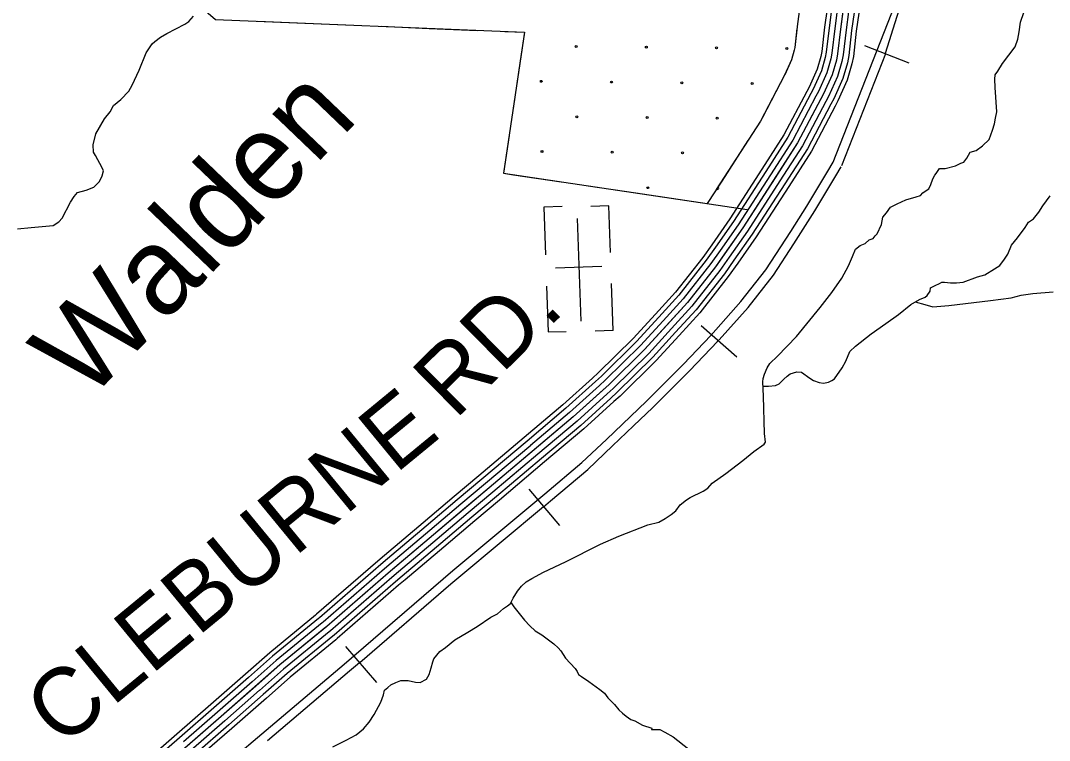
# Model space of a CAD drawing. Extents: x 1577619 to 1828281, y 483481 to 598136.
# Drawn here: x 1675742 to 1681374, y 510126 to 514068 of the extents above; entities that cross this region are included whole.
import ezdxf

# ---------------------------------------------------------------- set-up
doc = ezdxf.new("R2010")
doc.units = 0
for name, color, linetype in [('DESIGN - CONTOURS - Intermediate with optional Text', 7, 'Continuous'), ('DESIGN - DRAINAGE - Bridges and Cross Drains Size Text', 7, 'Continuous'), ('DESIGN - EROSION CONTROL - Devices', 7, 'Continuous'), ('DESIGN - ROW - Right-of-Way and Easement Labels', 7, 'Continuous'), ('DESIGN - TRANSPORTATION - Text', 7, 'Continuous'), ('DESIGN - UTILITIES - Cable (Underground) with Text', 7, 'Continuous'), ('SURVEY - TRANSPORTATION - Roads', 7, 'Continuous'), ('SURVEY - VEGETATION - Features with Text', 7, 'Continuous')]:
    doc.layers.add(name, color=color, linetype=linetype)

msp = doc.modelspace()

# ---------------------------------------------------------------- linework, layer by layer
at = {"layer": 'DESIGN - CONTOURS - Intermediate with optional Text'}
for p, q in [((1680362.2, 513931.6), (1680604.2, 513836.6)), ((1679662.5, 512223.8), (1679467.7, 512395.9)), ((1678693.2, 511302.3), (1678526.6, 511502)), ((1677692.7, 510443.5), (1677522.8, 510640.3))]:
    msp.add_line(p, q, dxfattribs=at)
for points in [[(1680189.5, 513292.2), (1680607.7, 514357.5), (1680665.4, 514468.9), (1680691.8, 514511.6), (1680818, 514688.1), (1680909.7, 514821.1), (1681031.8, 514985.7), (1681222.8, 515221.4), (1681354.8, 515377.9), (1681517, 515547.9), (1681654.6, 515676.2), (1681889.3, 515891.4), (1682077.3, 516051), (1682307.4, 516222.2), (1682599.6, 516406.5), (1682925.9, 516594.3), (1683175.5, 516727.1), (1683431, 516853.8), (1683670.2, 516958.7), (1683862.5, 517052.8)], [(1680476.4, 513888.6), (1680603.4, 514296.5), (1680640.9, 514394.1), (1680689.7, 514510.4)], [(1680236.8, 513273.6), (1680477.9, 513888)], [(1674951, 508587.6), (1675078.1, 508661.1), (1675481.1, 508901.7), (1675782.4, 509112.4), (1676046.1, 509313.4), (1676456.1, 509648.1), (1677512.9, 510542.5), (1678108.9, 511056.8), (1678611.5, 511476.1), (1678813.4, 511646.9), (1678948.4, 511774.5), (1679168.8, 511983.5), (1679370.4, 512186.2), (1679519.7, 512344), (1679684, 512530.1), (1679821.1, 512703.3), (1679957.3, 512912.7), (1680046.6, 513052.1), (1680161.2, 513242.5), (1680189.5, 513292.2)], [(1679974.1, 512845.8), (1679999.8, 512885.3), (1680089.6, 513025.4), (1680204.8, 513216.9), (1680233.5, 513267.1)], [(1679566.5, 512318.6), (1679723.8, 512496.8), (1679863.3, 512673), (1679975.2, 512845.1)], [(1679097.6, 511848), (1679203.2, 511948.2), (1679405.8, 512151.9), (1679556.1, 512310.7), (1679564.6, 512320.3)], [(1678603.9, 511405.6), (1678643.1, 511438.4), (1678846.3, 511610.2), (1678982.2, 511738.7), (1679097.5, 511848.1)], [(1678098, 510983.1), (1678140.4, 511019.7), (1678603.6, 511406)], [(1677598.2, 510552), (1678097.9, 510983.2)], [(1677093.4, 510126.1), (1677543.3, 510506.9), (1677597.1, 510553.3)]]:
    msp.add_lwpolyline(points, dxfattribs=at)
at = {"layer": 'DESIGN - EROSION CONTROL - Devices'}
for centre in [(1678782.8, 513925.3), (1679167.3, 513921.6), (1679551.9, 513917.8), (1679936.4, 513914.1), (1678592.4, 513734.9), (1678976.9, 513731.2), (1679361.5, 513727.4), (1679746, 513723.7), (1678786.5, 513540.7), (1679171.1, 513537), (1679555.6, 513533.3), (1678596.1, 513350.3), (1678980.7, 513346.6), (1679365.2, 513342.9), (1679174.8, 513152.5)]:
    msp.add_circle(centre, 5.28, dxfattribs=at)
msp.add_arc((1679559.4, 513148.7), 5.28, 0.5655, 293.7882, dxfattribs=at)
at = {"layer": 'DESIGN - TRANSPORTATION - Text'}
for points in [[(1678605.1, 511046.9), (1678725.6, 511103.5), (1678916.5, 511201.3), (1679016.9, 511244.1), (1679175.4, 511306.2), (1679235.4, 511321.5), (1679269.6, 511341.1), (1679303.8, 511362.7), (1679328, 511382.4), (1679352.4, 511416.2), (1679386.7, 511443.8), (1679406.8, 511455.5), (1679479.1, 511490.7), (1679503.2, 511506.4), (1679527.5, 511534.1), (1679602, 511587.3), (1679694.7, 511658.2), (1679755.2, 511707.5), (1679811.6, 511748.9), (1679819.7, 511758.8), (1679814.3, 511806.9), (1679808.8, 512011.2), (1679805.7, 512089.4), (1679805.9, 512107.4), (1679814.2, 512131.3), (1679828.6, 512165.2), (1679842.8, 512189), (1679885.3, 512230.6), (1679988.4, 512337.4), (1680118.1, 512496), (1680183, 512579.3), (1680237.8, 512656.7), (1680274.6, 512724.3), (1680295.1, 512776.1), (1680311.6, 512816), (1680337.8, 512835.7), (1680365.9, 512847.4), (1680386.1, 512867.1), (1680408.1, 512874.9), (1680420.3, 512888.7), (1680430.4, 512900.6), (1680455, 512950.4), (1680461.4, 512990.3), (1680481.7, 513014.1), (1680504, 513045.9), (1680540.2, 513063.5), (1680588.4, 513086.9), (1680644.5, 513102.2), (1680668.5, 513109.9), (1680680.7, 513123.8), (1680698.8, 513137.6), (1680712.9, 513145.4), (1680725.2, 513169.3), (1680735.5, 513201.2), (1680745.7, 513221.1), (1680753.9, 513231), (1680772.1, 513256.8), (1680802.1, 513258.5), (1680860.2, 513271.8), (1680888.3, 513287.4), (1680904.4, 513293.2), (1680920.6, 513315.1), (1680939, 513346.9), (1680973, 513356.5), (1681007.3, 513382.1), (1681043.6, 513415.7), (1681062.2, 513467.5), (1681072.6, 513501.4), (1681079, 513533.4), (1681085.4, 513567.3), (1681077, 513701.6), (1681075.5, 513747.7), (1681075.8, 513769.7), (1681092, 513791.5), (1681116.5, 513833.3), (1681151, 513878.9), (1681185.5, 513924.5), (1681199.9, 513966.4), (1681208.4, 514006.3), (1681215, 514058.3), (1681233.6, 514112.2)], [(1675725.8, 512928.1), (1675799.7, 512935.2), (1675919.7, 512945.7), (1675951.9, 512965.3), (1675970.1, 512985.1), (1676015, 513072.7), (1676035.4, 513104.5), (1676053.6, 513126.3), (1676101.7, 513139.7), (1676143.8, 513155.2), (1676174.2, 513186.8), (1676188.5, 513216.7), (1676196.8, 513244.6), (1676189, 513260.8), (1676151.9, 513329.3), (1676142.1, 513347.4), (1676138.6, 513387.5), (1676153.3, 513447.4), (1676202.2, 513528.9), (1676232.6, 513568.6), (1676251, 513602.4), (1676291.3, 513635.9), (1676333.8, 513681.5), (1676352.2, 513713.3), (1676391.1, 513796.9), (1676430.2, 513890.5), (1676462.7, 513940.2), (1676476.8, 513954), (1676507.1, 513977.7), (1676543.2, 513997.3), (1676641.7, 514048.1), (1676663.8, 514061.8), (1676688.1, 514091.6)], [(1679806.5, 512066), (1679835.1, 512066.4), (1679875.1, 512070), (1679895.2, 512077.7), (1679919.4, 512103.4), (1679937.6, 512121.2), (1679953.7, 512133.1), (1679991.8, 512144.6), (1680015.8, 512142.3), (1680061.3, 512109.7), (1680083.1, 512097.4), (1680112.9, 512085), (1680136.9, 512082.7), (1680164.9, 512088.4), (1680182.9, 512096.2), (1680197, 512106), (1680239.7, 512165.6), (1680260.1, 512203.4), (1680280.7, 512255.2), (1680313, 512284.8), (1680397.7, 512351.8), (1680478.2, 512408.9), (1680546.7, 512458.1), (1680615.3, 512513.4), (1680661.5, 512540.8), (1680693.6, 512552.4), (1680703.7, 512562.3), (1680720, 512586.2), (1680722.2, 512604.1), (1680748.3, 512617.8), (1680772.4, 512627.6), (1680784.4, 512635.4), (1680798.4, 512635.2), (1680832.3, 512630.8), (1680864.3, 512632.4), (1680902.3, 512636), (1680980.5, 512665), (1681020.6, 512674.6), (1681072.9, 512708), (1681103, 512725.6), (1681127.4, 512761.3), (1681145.7, 512789.2), (1681166.3, 512837), (1681198.7, 512878.6), (1681241.3, 512934.1), (1681259.6, 512963.9), (1681285.8, 512981.6), (1681316.2, 513019.3), (1681336.6, 513053.1), (1681377.2, 513108.7)], [(1680638.8, 512527.3), (1680691.1, 512512.4), (1680734.9, 512499.9), (1680822.9, 512506.8), (1681050.8, 512534), (1681164.8, 512548.6), (1681218.9, 512564), (1681282.9, 512573.2), (1681394.9, 512581.8)], [(1677451.5, 510090), (1677523.8, 510127.2), (1677578.1, 510156.5), (1677618.4, 510190.1), (1677650.8, 510225.7), (1677677.3, 510267.4), (1677714, 510335.1), (1677728.5, 510374.9), (1677734.8, 510400.9), (1677752.9, 510414.7), (1677769.1, 510430.5), (1677795.2, 510442.2), (1677823.3, 510453.9), (1677863.2, 510453.4), (1677903, 510444.9), (1677929, 510442.5), (1677963.2, 510462.1), (1677979.4, 510486), (1677989.9, 510523.9), (1677998.2, 510555.8), (1678004.4, 510571.8), (1678036.8, 510613.4), (1678067.1, 510635.1), (1678119.5, 510676.5), (1678189.9, 510717.7), (1678242.1, 510749), (1678316.6, 510800.2), (1678352.8, 510819.8), (1678385.1, 510847.4), (1678407.3, 510863.2), (1678423.4, 510875), (1678437.7, 510904.8), (1678462.1, 510942.6), (1678484.4, 510970.3), (1678508.7, 510994.1), (1678540.8, 511011.7), (1678605.1, 511046.9)], [(1678427.7, 510879.4), (1678442.6, 510858.1), (1678499.8, 510783.4), (1678529.5, 510753.1), (1678559.1, 510726.8), (1678594.9, 510704.4), (1678660.3, 510655.6), (1678684, 510633.3), (1678699.8, 510617.2), (1678725.4, 510576.8), (1678776.8, 510520.2), (1678788.6, 510504.1), (1678796.4, 510486), (1678812.3, 510475.8), (1678851.9, 510449.3), (1678913.4, 510404.7), (1678939.1, 510384.4), (1678956.9, 510358.1), (1678992.4, 510321.7), (1679016.1, 510293.4), (1679035.9, 510275.2), (1679057.7, 510259), (1679081.5, 510240.7), (1679103.4, 510232.5), (1679147.1, 510210), (1679196.8, 510193.4), (1679194.8, 510185.4), (1679240.7, 510185), (1679268.5, 510170.7), (1679314.2, 510146.2), (1679399.3, 510077.2)]]:
    msp.add_lwpolyline(points, dxfattribs=at)
at = {"layer": 'DESIGN - UTILITIES - Cable (Underground) with Text'}
for p, q in [((1678606.2, 513045.3), (1678615.3, 512784.6)), ((1678705.8, 513048.7), (1678606.8, 513045.3)), ((1678962.5, 513053.7), (1678862.8, 513050.2)), ((1678971.4, 512797.1), (1678962.4, 513053.7)), ((1678924, 512721), (1678670.5, 512712.2)), ((1678986.3, 512370.9), (1678977.2, 512628.8)), ((1678621.3, 512613.7), (1678630.1, 512362.4)), ((1678630.2, 512362.4), (1678728.4, 512365.8)), ((1678986.1, 512370.9), (1678886.7, 512367.4))]:
    msp.add_line(p, q, dxfattribs=at)
msp.add_lwpolyline([(1678789.4, 512984.2), (1678809.1, 512421.5)], dxfattribs=at)
at = {"layer": 'SURVEY - TRANSPORTATION - Roads'}
for points in [[(1680629, 517094.8), (1680457.4, 515734.2), (1680322.3, 514710.7), (1680262.6, 514270.9), (1680229.4, 514021), (1680213.6, 513885), (1680207.2, 513851), (1680184.2, 513771.3), (1680136.9, 513665.7), (1679995.5, 513397.3), (1679695.8, 512932.7), (1679545.2, 512718.4), (1679392.9, 512524.2), (1679157.8, 512267), (1678963.6, 512075.3), (1678767.5, 511897.7), (1678307, 511509.3), (1678002, 511251), (1677753.6, 511042.1), (1677418.2, 510750.2), (1677161.8, 510539.3), (1676840.5, 510257.2), (1676286.9, 509774)], [(1680156.6, 514131.3), (1680143.3, 514031.7), (1680127.8, 513898.1), (1680122.8, 513871.2), (1680102.6, 513801.2), (1680058.9, 513703.7), (1680046.1, 513679.5)], [(1680181.1, 514128), (1680167.9, 514028.6), (1680152.3, 513894.4), (1680146.8, 513865.4), (1680125.8, 513792.6), (1680081.1, 513692.9), (1680068, 513668)], [(1680211.8, 514123.9), (1680198.6, 514024.8), (1680183, 513889.7), (1680177, 513858.2), (1680155, 513781.9), (1680109, 513679.3), (1680095.4, 513653.5)], [(1680242.5, 514119.9), (1680229.4, 514021), (1680213.6, 513885), (1680207.2, 513851), (1680184.2, 513771.3), (1680136.9, 513665.7), (1680122.8, 513639.1)], [(1680273.3, 514115.8), (1680260.2, 514017.2), (1680244.3, 513880.3), (1680237.4, 513843.8), (1680213.4, 513760.6), (1680164.7, 513652.2), (1680150.3, 513624.6)], [(1680304, 514111.7), (1680290.9, 514013.3), (1680275, 513875.7), (1680267.6, 513836.7), (1680242.5, 513749.9), (1680192.6, 513638.6), (1680177.7, 513610.2)], [(1680329.5, 514108.3), (1680316.4, 514010.2), (1680300.4, 513871.8), (1680292.6, 513830.7), (1680266.7, 513741), (1680215.8, 513627.3), (1680200.4, 513598.2)], [(1680046.1, 513679.5), (1679920.6, 513441.1), (1679799.8, 513253.8)], [(1680068, 513668), (1679942, 513428.6), (1679820.5, 513240.4)], [(1680095.4, 513653.5), (1679968.8, 513412.9), (1679846.6, 513223.6)], [(1680122.8, 513639.1), (1679995.5, 513397.3), (1679872.6, 513206.7)], [(1680150.3, 513624.7), (1680022.3, 513381.6), (1679898.7, 513189.9)], [(1680177.7, 513610.2), (1680049.1, 513366), (1679924.7, 513173.1)], [(1680200.5, 513598.2), (1680071.4, 513353), (1679946.4, 513159.2)], [(1679799.8, 513253.8), (1679623.9, 512981.1), (1679525, 512840.3)], [(1679820.6, 513240.4), (1679644.4, 512967.3), (1679545.2, 512826.1)], [(1679846.6, 513223.6), (1679670.1, 512950), (1679570.5, 512808.3)], [(1679872.7, 513206.8), (1679695.8, 512932.7), (1679595.9, 512790.4)], [(1679898.7, 513189.9), (1679721.6, 512915.3), (1679621.2, 512772.6)], [(1679924.8, 513173.1), (1679747.3, 512898), (1679646.6, 512754.8)], [(1679946.4, 513159.2), (1679768.6, 512883.6), (1679667.6, 512740)], [(1679525, 512840.3), (1679475.6, 512770.1), (1679326.7, 512580.2), (1679217.5, 512460.8)], [(1679545.2, 512826.1), (1679495.5, 512755.4), (1679345.6, 512564.3), (1679235.8, 512444.1)], [(1679570.5, 512808.3), (1679520.4, 512736.9), (1679369.2, 512544.2), (1679258.7, 512423.2)], [(1679595.9, 512790.5), (1679545.2, 512718.4), (1679392.9, 512524.2), (1679281.5, 512402.3)], [(1679621.3, 512772.6), (1679570.1, 512699.9), (1679416.6, 512504.1), (1679304.4, 512381.4)], [(1679646.6, 512754.8), (1679595, 512681.4), (1679440.2, 512484.1), (1679327.3, 512360.5)], [(1679667.7, 512740), (1679615.7, 512666.1), (1679459.9, 512467.4), (1679346.3, 512343.1)], [(1679217.6, 512460.8), (1679095.3, 512327.1), (1678904, 512138.3), (1678873, 512110.2)], [(1679235.8, 512444.2), (1679113.2, 512310), (1678921, 512120.4), (1678889.6, 512091.9)], [(1679258.7, 512423.2), (1679135.5, 512288.5), (1678942.3, 512097.8), (1678910.4, 512068.9)], [(1679281.6, 512402.3), (1679157.8, 512267), (1678963.6, 512075.3), (1678931.2, 512045.9)], [(1679304.4, 512381.4), (1679180.2, 512245.4), (1678984.9, 512052.8), (1678952, 512023)], [(1679327.3, 512360.5), (1679202.5, 512223.9), (1679006.2, 512030.2), (1678972.8, 512000)], [(1679346.3, 512343.1), (1679221.1, 512206.1), (1679023.8, 512011.5), (1678990.1, 511980.9)], [(1678873, 512110.2), (1678710.4, 511963), (1678498.2, 511784)], [(1678889.6, 512091.9), (1678726.7, 511944.4), (1678514.2, 511765.1)], [(1678910.4, 512068.9), (1678747.1, 511921), (1678534.1, 511741.4)], [(1678931.2, 512046), (1678767.5, 511897.7), (1678554.1, 511717.7)], [(1678952, 512023), (1678787.9, 511874.3), (1678574.1, 511694)], [(1678972.8, 512000), (1678808.3, 511851), (1678594.1, 511670.3)], [(1678990.1, 511980.9), (1678825.2, 511831.6), (1678610.7, 511650.7)], [(1678498.2, 511784), (1678251, 511575.5), (1678116.1, 511461.3)], [(1678514.2, 511765.1), (1678267, 511556.7), (1678132.1, 511442.4)], [(1678534.2, 511741.4), (1678287, 511533), (1678152.1, 511418.8)], [(1678554.1, 511717.7), (1678307, 511509.3), (1678172.2, 511395.1)], [(1678574.1, 511694), (1678327, 511485.6), (1678192.2, 511371.4)], [(1678594.1, 511670.3), (1678347, 511462), (1678212.2, 511347.8)], [(1678610.7, 511650.7), (1678363.6, 511442.3), (1678228.8, 511328.2)], [(1678116.1, 511461.3), (1677946.1, 511317.3), (1677734.2, 511139.1)], [(1678132.1, 511442.4), (1677962, 511298.4), (1677750.1, 511120.1)], [(1678152.1, 511418.8), (1677982, 511274.7), (1677770, 511096.4)], [(1678172.2, 511395.1), (1678002, 511251), (1677790, 511072.7)], [(1678192.2, 511371.5), (1678022, 511227.3), (1677810, 511049)], [(1678212.2, 511347.8), (1678042, 511203.7), (1677829.9, 511025.2)], [(1678228.8, 511328.2), (1678058.6, 511184), (1677846.5, 511005.6)], [(1677734.2, 511139.1), (1677697.2, 511108), (1677362.2, 510816.4), (1677357.2, 510812.2)], [(1677750.1, 511120.2), (1677713.3, 511089.2), (1677378.2, 510797.5), (1677372.8, 510793.1)], [(1677770.1, 511096.4), (1677733.5, 511065.6), (1677398.2, 510773.8), (1677392.5, 510769.2)], [(1677790, 511072.7), (1677753.6, 511042.1), (1677418.2, 510750.2), (1677412.2, 510745.2)], [(1677810, 511049), (1677773.8, 511018.5), (1677438.2, 510726.5), (1677431.9, 510721.3)], [(1677829.9, 511025.3), (1677793.9, 510995), (1677458.2, 510702.8), (1677451.5, 510697.3)], [(1677846.5, 511005.6), (1677810.6, 510975.4), (1677474.8, 510683.2), (1677467.9, 510677.4)], [(1677357.1, 510812.2), (1677105.6, 510605.4), (1676972.5, 510488.5)], [(1677372.8, 510793.1), (1677121.6, 510586.6), (1676988.8, 510469.9)], [(1677392.5, 510769.2), (1677141.7, 510562.9), (1677009.2, 510446.6)], [(1677412.2, 510745.2), (1677161.8, 510539.3), (1677029.7, 510423.3)], [(1677431.9, 510721.3), (1677181.9, 510515.7), (1677050.1, 510400)], [(1677451.6, 510697.3), (1677201.9, 510492.1), (1677070.6, 510376.7)], [(1677467.9, 510677.5), (1677218.6, 510472.5), (1677087.6, 510357.4)], [(1676972.5, 510488.5), (1676783.4, 510322.5), (1676596.5, 510159.3)], [(1676988.8, 510469.9), (1676799.7, 510303.9), (1676612.7, 510140.7)], [(1677009.3, 510446.6), (1676820.1, 510280.6), (1676633.1, 510117.4)], [(1677029.7, 510423.4), (1676840.5, 510257.2), (1676653.5, 510094)], [(1677050.2, 510400.1), (1676860.9, 510233.9), (1676673.9, 510070.6)], [(1677070.6, 510376.8), (1676881.3, 510210.6), (1676694.3, 510047.3)], [(1677087.6, 510357.4), (1676898.3, 510191.2), (1676711.2, 510027.9)], [(1676596.5, 510159.3), (1676231.7, 509841), (1676223.2, 509834.3)], [(1676612.7, 510140.7), (1676247.5, 509821.9), (1676238.3, 509814.8)]]:
    msp.add_lwpolyline(points, dxfattribs=at)
at = {"layer": 'SURVEY - VEGETATION - Features with Text'}
for points in [[(1676406.6, 517349.5), (1676137.8, 515434.9), (1677424, 515261.7), (1676535.4, 514193.5), (1676717.5, 514153.4), (1676716.7, 514154.2), (1676808.3, 514074.2), (1678499.9, 514003.3), (1678385.6, 513231.5), (1679719.1, 513033.3)], [(1680394.6, 517124.4), (1680223.1, 515764.5), (1680088, 514742), (1680028.4, 514302.3), (1679994.9, 514050.2), (1679979.9, 513920.6), (1679977.1, 513905.9), (1679961.8, 513852.8), (1679924.3, 513769.2), (1679791.3, 513516.6), (1679550, 513142.4)], [(1677038.2, 514064.6), (1677302, 514053.5)], [(1677302, 514053.5), (1677565.8, 514042.4)], [(1677715.6, 514036.2), (1677979.4, 514025.1)], [(1677979.4, 514025.1), (1678243.2, 514014)], [(1678393, 514007.7), (1678499.9, 514003.3), (1678476.9, 513848)], [(1679991.9, 514024.4), (1679979.9, 513920.6), (1679977.1, 513905.9), (1679961.8, 513852.8), (1679925.2, 513771.3)], [(1678476.9, 513848), (1678438.2, 513586.8)], [(1679925.2, 513771.3), (1679924.3, 513769.2), (1679802.4, 513537.7)], [(1678416.2, 513438.4), (1678385.6, 513231.5), (1678439.8, 513223.5)], [(1679722.9, 513410.5), (1679579.8, 513188.7)], [(1678439.8, 513223.5), (1678700.9, 513184.6)], [(1678849.3, 513162.6), (1679110.4, 513123.8)], [(1679579.8, 513188.7), (1679500.5, 513065.8)], [(1679110.4, 513123.8), (1679500.5, 513065.8)]]:
    msp.add_lwpolyline(points, dxfattribs=at)

# ---------------------------------------------------------------- texts
at = {"layer": 'DESIGN - DRAINAGE - Bridges and Cross Drains Size Text'}
msp.add_text('Walden', height=475, rotation=46.2259, dxfattribs=at).set_placement((1676107.8, 511972.8))
at = {"layer": 'DESIGN - ROW - Right-of-Way and Easement Labels'}
for s, rotation, p in [('RD.', 44.6158, (1678120.5, 511877.8)), ('CLEBURNE', 39.43, (1675967.4, 510079.8))]:
    msp.add_text(s, height=370, rotation=rotation, dxfattribs=at).set_placement(p)

doc.saveas('drawing.dxf')
